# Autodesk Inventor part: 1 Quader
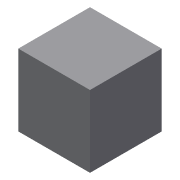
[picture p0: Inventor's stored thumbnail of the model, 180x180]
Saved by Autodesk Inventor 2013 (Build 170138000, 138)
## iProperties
Created: 2012-10
Part Number: 1 Quader
Material: Allgemein
Vendor: www.inventor-faq.de
Document SubType Name: Modeling
Designer: Administrator
Manufacturer: www.inventor-faq.de
Density: 1 g/cm^3
RuleStatus: InUse
AfterDocOpen0: inventorfaq
BeforeDocSave0: inventorfaq
Author: Administrator
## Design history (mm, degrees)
sketch "Skizze1"
  geometry: L1 (-5, -5)-(5, -5); L2 (5, -5)-(5, 5); L3 (5, 5)-(-5, 5); L4 (-5, 5)-(-5, -5); L5 (-5, -5)-(5, 5); L6 (5, -5)-(-5, 5); 1 further point
  constraints: 12 end point, 2 midpoint, 2 parallel, 1 horizontal, 1 perpendicular
  dimensions: "d0" = 10 distance of L3.end L2.end; "d1" = 10 distance of L2.end L1.end
extrude "Extrusion1" new body sketch "Skizze1" distance "d2" = 10; taper "d3" = 0 deg
node "Volumenkörper1"
